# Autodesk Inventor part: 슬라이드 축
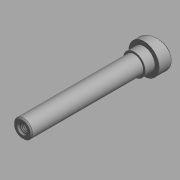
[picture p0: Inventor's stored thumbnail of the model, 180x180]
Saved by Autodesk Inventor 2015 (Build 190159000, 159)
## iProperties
Created: 2015-11
Part Number: 슬라이드 축
Document SubType Name: 모델링
Designer: mdu
Mass: 174.309 g
Surface Area: 67.586 cm^2
Volume: 21.5729 cm^3
Density: 8.08 g/cm^3
Material: 스테인리스강
Appearance: 기본값
변환 표준: STEP AP214IS
파일 이름: C:\Users\SeoGD\Desktop\?쒗뿕\異?stp
전처리기: Build: 253, Release: 2010 SP1 - Date: Wed 07/29/2009
전송 단위: 밀리미터
불확실성: 0.01
Author: mdu
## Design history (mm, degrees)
sketch "스케치1"
  geometry: L1 (0, 100)-(7.5, 100); L2 (7.5, 100)-(7.5, 0); L3 (7.5, 0)-(12.5, 0); L4 (12.5, 0)-(12.5, -17); L5 (12.5, -17)-(0, -17); L6 (0, -17)-(0, 100); 1 further point
  constraints: 12 end point, 2 parallel, 2 point on line, 1 perpendicular, 1 vertical
  dimensions: "d0" = 100 distance from line of L1 point (0, 0); "d1" = 15 diameter of L2 L6; "d2" = 25 diameter of L4 L6; "d3" = 17 distance of L3.end L4.end
revolve "회전1" sketch "스케치1" stored, may be unused: angle "d4" = 90 deg
sketch "스케치2"
  geometry: L1 (12.5, 0)-(12.5, -17) reference; L2 (-12.5, -17)-(12.5, -17) reference; L3 (-12.5, 0)-(-12.5, -17) reference; L4 (12.5, -5)-(-12.5, -11.699); L5 (-12.5, 0)-(12.5, 0) reference; 1 further point
  constraints: 2 end point, 2 point on line
  dimensions: "d5" = 75 deg angle of L1 L4; "d6" = 5 distance from line of L4.start L5
extrude "돌출1" cut sketch "스케치2" stored distance "d7" = 10; taper "d8" = 0 deg
chamfer "모따기1" distance "d9" = 1; stored, may be unused: second distance "d10" = 2, angle "d11" = 45 deg
fillet "모깎기1" dims "d12" = 0.5
hole "구멍1" diameter "d15" = 6.647; stored, may be unused: countersink angle "d19" = 90 deg, drill point angle "d21" = 118 deg; dims "d13" = 10, "d14" = 10, "d16" = 17, "d17" = 4, "d18" = 2, "d20" = 20
chamfer "모따기2" distance "d22" = 1; stored, may be unused: second distance "d23" = 2, angle "d24" = 45 deg
sketch "스케치3"
  geometry: C1 r 9 at (0, 0); 1 further point
  constraints: 1 centre point, 1 coincident
  dimensions: "d25" = 18 diameter of C1
extrude "돌출2" join sketch "스케치3" distance "d26" = 8; taper "d27" = 0 deg
node "솔리드1"
node "솔리드 본체"
node "곡면 본체"
node "솔리드2"
